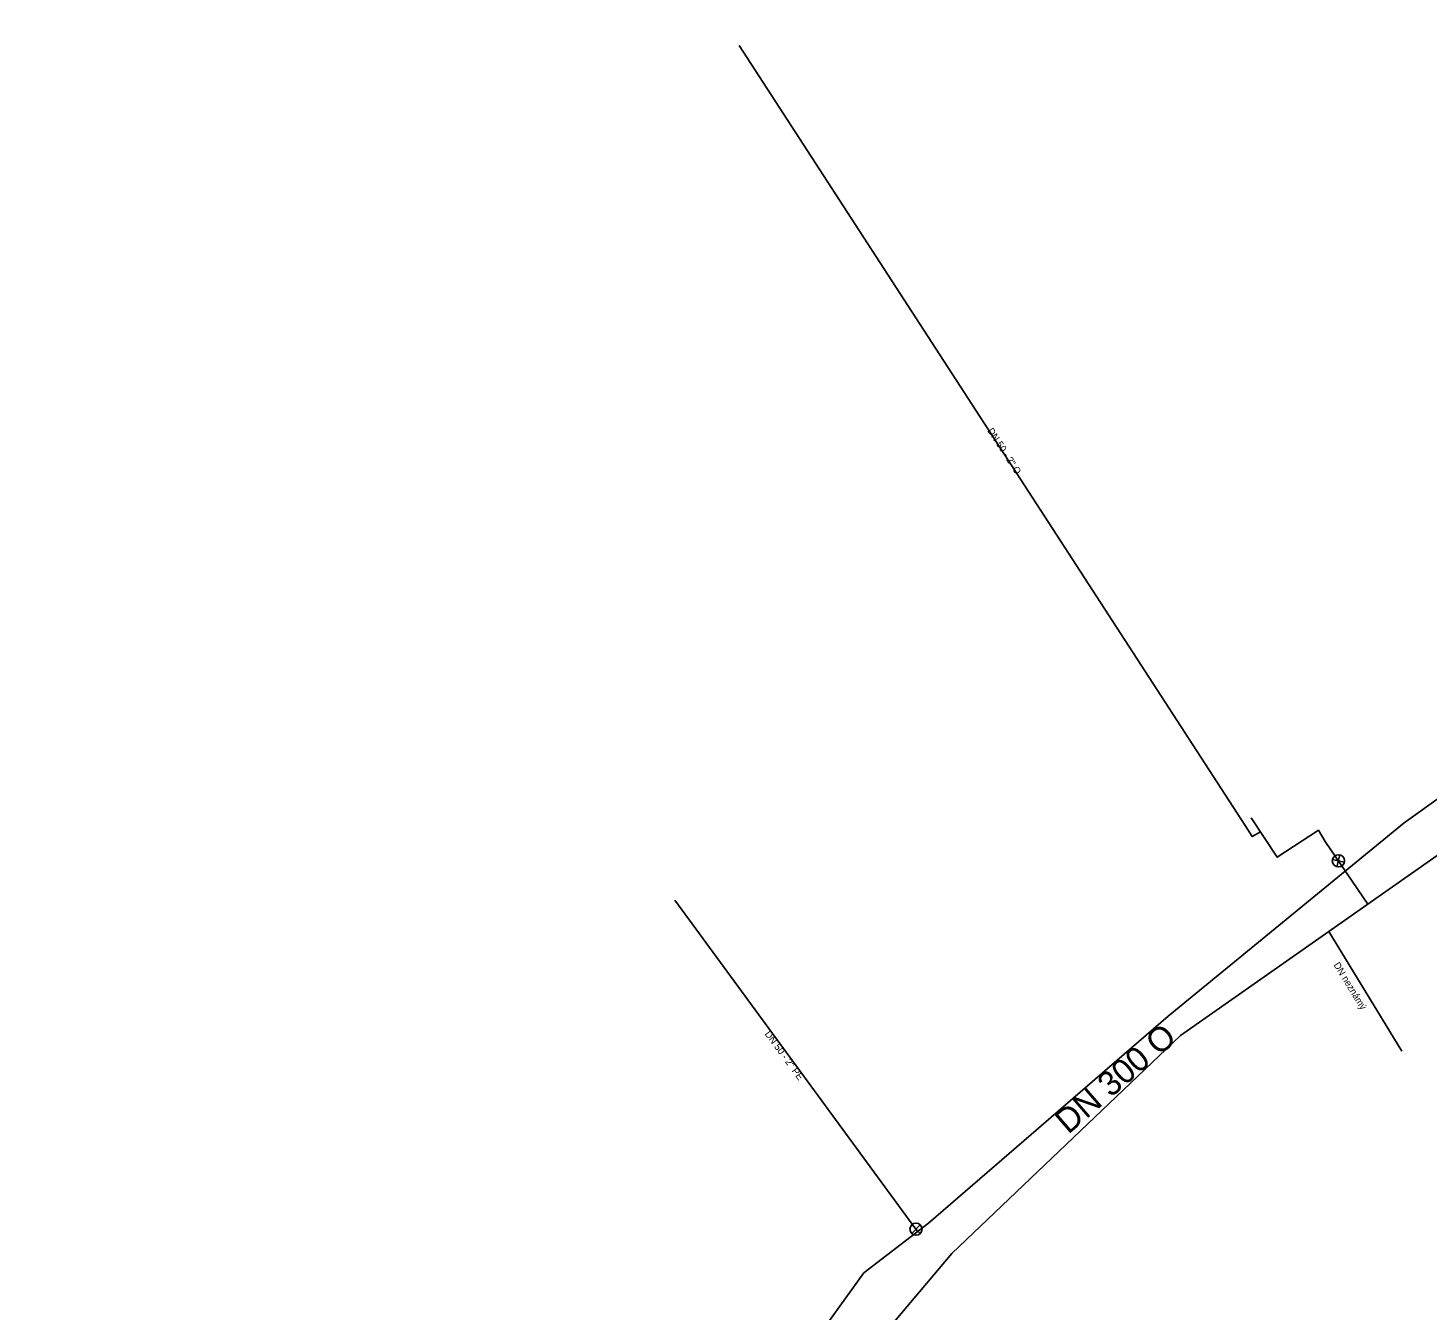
# Model space of a CAD drawing. Extents: x -4927528 to -4924018, y -11264917 to -11262544.
# Drawn here: x -4927375 to -4926456, y -11264100 to -11263258 of the extents above; entities that cross this region are included whole.
import ezdxf

# ---------------------------------------------------------------- set-up
doc = ezdxf.new("R2010")
doc.units = 0
for name, color, linetype in [('_pripojka_prevzato_z_dokumentace_', 7, 'Continuous'), ('_pripojka_priblizne_', 7, 'Continuous'), ('_voda_smvak_prevzato_z_dokumentace_', 7, 'Continuous'), ('Default', 7, 'Continuous'), ('MoLevel 32', 7, 'Continuous'), ('MoLevel 46', 7, 'Continuous'), ('MoLevel 53', 7, 'Continuous'), ('MoLevel 55', 7, 'Continuous')]:
    doc.layers.add(name, color=color, linetype=linetype)

# ---------------------------------------------------------------- blocks, each defined once
blk = doc.blocks.new('_uzaver_pripojka_')
at = {"layer": 'Default'}
for p, q in [((-0.00035, -0.00035), (0.00035, 0.00035)), ((0.00035, -0.00035), (-0.00035, 0.00035))]:
    blk.add_line(p, q, dxfattribs=at)
for radius in [0.0005, 0.000025]:
    blk.add_circle((0, 0), radius, dxfattribs=at)

msp = doc.modelspace()

# ---------------------------------------------------------------- linework, layer by layer
at = {"layer": '_pripojka_prevzato_z_dokumentace_'}
msp.add_line((-4926472.85, -11263929.62), (-4926520.91, -11263850.96), dxfattribs=at)
at = {"layer": '_pripojka_priblizne_'}
msp.add_line((-4926575.89, -11263781.34), (-4926908.12, -11263269.09), dxfattribs=at)
for points in [[(-4926575.89, -11263781.34), (-4926571.13, -11263788.69), (-4926565.83, -11263785.6)], [(-4926571.91, -11263776.41), (-4926554.77, -11263802.27), (-4926527.71, -11263784.58), (-4926523.29, -11263791.87), (-4926495.23, -11263832.99)], [(-4926790.91, -11264048.14), (-4926792.07, -11264046.56), (-4926950.44, -11263830.55)]]:
    msp.add_lwpolyline(points, dxfattribs=at)
at = {"layer": '_voda_smvak_prevzato_z_dokumentace_'}
for points in [[(-4925741.8, -11263257.7), (-4926471.3, -11263779.67), (-4926626.34, -11263906.72), (-4926783.75, -11264042.66), (-4926826.31, -11264075.24), (-4926870.7, -11264137.04), (-4927005.3, -11264324.44), (-4927247.9, -11264639.15), (-4927375.4, -11264800)], [(-4926437.33, -11263792.47), (-4926527.46, -11263855.55), (-4926618.25, -11263919.35), (-4926768.54, -11264062.51), (-4926828.65, -11264133.88), (-4926875.74, -11264199.09), (-4927005.98, -11264381.89), (-4927278.64, -11264765.71), (-4927326.86, -11264843.57)]]:
    msp.add_lwpolyline(points, dxfattribs=at)

# ---------------------------------------------------------------- block references
at = {"layer": 'MoLevel 53', "xscale": 8000, "yscale": 7999.999999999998, "rotation": 31.485847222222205}
msp.add_blockref('_uzaver_pripojka_', (-4926514.58, -11263804.63), dxfattribs=at)
at = {"layer": 'MoLevel 53', "xscale": 7999.999999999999, "yscale": 7999.999999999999}
msp.add_blockref('_uzaver_pripojka_', (-4926792.07, -11264046.56), dxfattribs=at)

# ---------------------------------------------------------------- texts
at = {"layer": 'MoLevel 32'}
for s, rotation, p in [("DN 50 - 2'' O", 302.96605, (-4926745.36, -11263522.17)), ("DN 50 - 2'' PE", 306.2474, (-4926891.7, -11263918.36))]:
    msp.add_text(s, height=4.55, rotation=rotation, dxfattribs=at).set_placement(p)
at = {"layer": 'MoLevel 46'}
msp.add_text('DN 300 O', height=16.049, rotation=40.81404, dxfattribs=at).set_placement((-4926692.04, -11263984.66))
at = {"layer": 'MoLevel 55'}
msp.add_text('DN neznámý', height=4.55, rotation=301.424, dxfattribs=at).set_placement((-4926517.94, -11263872.94))

doc.saveas('drawing.dxf')
